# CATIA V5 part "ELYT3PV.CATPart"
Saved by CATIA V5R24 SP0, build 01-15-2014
Part number: ELYT3PV
Material "ZAMA": density 6700 kg/m3
Material "ZAMA": density 6700 kg/m3
Bounding box of the stored display mesh (mm): x -59 to 27.5, y 0 to 1560, z 0 to 1500
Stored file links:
  \\mnsrv021stg\Common\AREA TECNICA\Documenti\3D sito\BOX\ELYT\ZEPHYR3P\ELYT3PV.CATPart
  Z:\commesse\Novellini\Serie Zephiros\BH01S66\ID_18668_00.CATPart
  Z:\commesse\Novellini\Prove\Tabelladiprogetto1.txt
  Z:\commesse\Novellini\Prove\Tabelladiprogetto2.xls
  C:\Users\n.rebecchi\Desktop\Scambio\ID_35222_00.xls
  Z:\3D sito\BH02A.xlsx
  \\MNSRV021STG\Common\AREA TECNICA\Documenti\3D sito\BOX\ZEPHIROS\BH02A\BH02A.xls
  Z:\3D sito\ZEPHIROS\BH022P\BH022P.xls
  C:\Docisland\DocIsland\catia_workdir\diclient\N.REBECCHI\ID_21111_03.CATPart
  C:\Docisland\DocIsland\catia_workdir\diclient\N.REBECCHI\ID_29051_00.CATPart
  U:\AREA TECNICA\Documenti\3D sito\BOX\ZEPHYROS\ZEPHYR3P\BH013P.xls
  \\mnsrv021stg\Common\AREA TECNICA\Documenti\3D sito\BOX\ELYT\ZEPHYR3P\ELYT3PV.xls
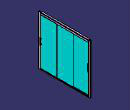
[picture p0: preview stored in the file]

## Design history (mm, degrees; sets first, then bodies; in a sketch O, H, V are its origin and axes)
Parameters
  `Larghezza anta` = 501 mm {design table}
  `MISURA NOMINALE` = 1560 mm {design table}
  PartNumber = "ELYT3PV156" {design table}
  `Lunghezza binario` = 1466 mm {design table}
Pad1: profile Sketch3.L13, length 1441, opposite side length -21
Solid1: solid without history
Solid2: solid without history
Pad2: profile Sketch3.L6, length 1441, opposite side length -21
Sketch1 on xy-plane, origin (0, 0, 0), H (1, 0, 0), V (0, 1, 0)
  axis line L1 (84.1025, 780) -> (-125.0839, 780)
  point P3 (-18.5, 0)
  point P4 (-18.5, 52.3)
  point P5 (0, 50.8)
  point P6 (-1.5, 52.3)
  point P8 (0, 1.5)
  point P9 (-1.5, 0)
  line L2 (0, 50.8) -> (0, 1.5)
  line L3 (-1.5, 0) -> (-32.75, 0)
  line L4 (-18.5, 1.5) -> (-18.5, 52.3)
  line L5 (-18.5, 52.3) -> (-1.5, 52.3)
  arc A1 centre (-1.5, 50.8) radius 1.5 from (0, 50.8) to (-1.5, 52.3) ccw
  arc A2 centre (-1.5, 1.5) radius 1.5 from (0, 1.5) to (-1.5, 0) cw
  line L6 (-18.5, 1.5) -> (-32.75, 1.5)
  point P11 (-32.75, 1.5)
  arc A3 centre (-32.75, 0.75) radius 0.75 from (-32.75, 1.5) to (-32.75, 0) ccw
  point P13 (-32.75, 0)
  point P14 (-18.5, 1.5)
  point P15 (-3, 1307.7)
  construction line L7 through (-1555.4, 0) direction (-1, 0)
  construction line L8 through (-1255.4, 0) direction (0, 1)
  point P16 (-18.5, 1560)
  point P17 (-18.5, 1507.7)
  point P18 (0, 1509.2)
  point P19 (-1.5, 1507.7)
  point P21 (0, 1558.5)
  point P22 (-1.5, 1560)
  point P24 (-32.75, 1558.5)
  point P26 (-32.75, 1560)
  point P27 (-18.5, 1558.5)
  line L9 (0, 1509.2) -> (0, 1558.5)
  line L10 (-1.5, 1560) -> (-32.75, 1560)
  line L11 (-18.5, 1558.5) -> (-18.5, 1509.1)
  line L12 (-52, 1507.7) -> (-1.5, 1507.7)
  arc A4 centre (-1.5, 1509.2) radius 1.5 from (0, 1509.2) to (-1.5, 1507.7) cw
  arc A5 centre (-1.5, 1558.5) radius 1.5 from (0, 1558.5) to (-1.5, 1560) ccw
  line L13 (-18.5, 1558.5) -> (-32.75, 1558.5)
  arc A6 centre (-32.75, 1559.25) radius 0.75 from (-32.75, 1558.5) to (-32.75, 1560) cw
  line L14 (-52, 1507.7) -> (-52, 1518.2)
  line L15 (-52, 1518.2) -> (-37, 1518.2)
  line L16 (-37, 1518.2) -> (-37, 1509.1)
  line L17 (-37, 1509.1) -> (-18.5, 1509.1)
  length L5 = 17
  radius A1 = 1.5
  distance L6 L3 = 1.5
  distance L4 A3 = 15
  distance L5 L3 = 52.3
  distance L2 L4 = 18.5
  radius A2 = 1.5
  distance L10 L3 = 1560 {= `MISURA NOMINALE`}
  distance L9 L14 = 52
  length L15 = 15
  distance L12 L17 = 1.4
  distance L15 L12 = 10.5
  tangency: A1 L2, A3 L3, A3 L6, L2 A2, A2 L3
  coincidence: P3 L3, P17 L11, P17 L12, L2 V, L3 L7, L3 H
  symmetry: P3 P16 L1, P4 P17 L1, P5 P18 L1, P6 P19 L1, P8 P21 L1, P9 P22 L1, P11 P24 L1, P13 P26 L1, P14 P27 L1, L2 L9 L1, L3 L10 L1, L4 L11 L1, L5 L12 L1, A1 A4 L1, A2 A5 L1, L6 L13 L1, A3 A6 L1
  vertical: L16 V
Pad3: profile Sketch1, direction (0, 0, 1), length 1500
Body1 "Telaio" (main body)
  Sketch2 on face of Pad3 from Sketch1.L5, origin (0, 52.3, 0), H (-1, 0, 0), V (0, 0, -1)
    point P1 (-1, -1500)
    line L1 (5.7859, -1500) -> (52.2221, -1500)
    line L2 (59, -1485.3692) -> (59, -1437.2118)
    construction line L3 (247.7599, -1440) -> (58, -1440)
    line L4 (-1, -1436.5) -> (-1, -1485.3692)
    point P2 (59, -1500)
    point P3 (59, -1440)
    construction line L5 (57.5, -1498) -> (57.5, -1486.5)
    construction line L6 (190.2599, -1498) -> (4.1139, -1498)
    point P5 (57.5, -1498)
    line L7 (57.7882, -1436) -> (-0.5, -1436)
    construction line L8 (8.597, -1485.5) -> (18.6226, -1485.5)
    construction line L9 (1.7786, -1486.5) -> (4.2562, -1486.5)
    construction line L10 (57.5, -1485.2) -> (57.5, -1440.5)
    construction line L11 (1, -1485) -> (1, -1464.277)
    point P6 (57.5, -1486.5)
    point P7 (1, -1485.5)
    construction line L12 (36.5779, -1495.9874) -> (36.5305, -1488.4874)
    construction line L13 (37.7781, -1496.0126) -> (37.7307, -1488.5126)
    construction line L14 (39.7307, -1486.5) -> (53.9552, -1486.5)
    construction line L15 (39.778, -1498) -> (50.7716, -1498)
    construction line L16 (18.9226, -1496) -> (18.9226, -1488.5)
    construction line L17 (20.1226, -1496) -> (20.1226, -1486.8)
    construction line L18 (20.4226, -1486.5) -> (34.5306, -1486.5)
    construction line L19 (22.1226, -1498) -> (34.5779, -1498)
    construction line L20 (18.9226, -1485.2) -> (18.9226, -1464.6071)
    construction line L21 (20.1226, -1485.2) -> (20.1226, -1466.4658)
    construction line L22 (36.5098, -1485.1981) -> (36.3815, -1464.8702)
    construction line L23 (37.7098, -1485.2019) -> (37.5963, -1467.2104)
    construction line L24 (20.4226, -1485.5) -> (222.4284, -1485.5)
    construction line L25 (38.0098, -1485.5) -> (57.2, -1485.5)
    construction line L26 (0.5, -1461.4168) -> (0.5, -1436.5)
    construction line L27 (46.4222, -1915.0185) -> (46.406, -1912.4534)
    construction line L28 (46.4222, -1915.0185) -> (47.9222, -1915.0091)
    construction arc A1 centre (8.7492, -1464.5115) radius 0.25 from (8.9992, -1464.5065) to (8.701, -1464.7568) cw
    construction arc A2 centre (5.7, -1465.25) radius 2.75 from (3.3803, -1463.773) to (8.3995, -1464.7254) cw
    point P12 (5.7, -1465.25)
    construction line L29 (1.4989, -1463.777) -> (3.3803, -1463.773)
    construction arc A3 centre (4.9238, -1464.5873) radius 4.0762 from (1.9856, -1461.762) to (9, -1464.5873) cw
    point P14 (8.9992, -1464.5065)
    construction arc A4 centre (8.7975, -1464.2662) radius 0.5 from (8.701, -1464.7568) to (8.321, -1464.4175) cw
    point P16 (8.321, -1464.4175)
    point P18 (23.1853, -1465.9683)
    point P19 (21.993, -1463.4903)
    point P20 (25.9312, -1465.8199)
    construction arc A5 centre (23.1853, -1465.9683) radius 2.75 from (21.993, -1463.4903) to (25.9123, -1465.6134) cw
    construction arc A6 centre (26.4305, -1465.7929) radius 0.5 from (25.9918, -1465.553) to (25.9312, -1465.8199) cw
    construction arc A7 centre (26.2112, -1465.6729) radius 0.25 from (26.45, -1465.7469) to (25.9918, -1465.553) cw
    construction arc A8 centre (23.4246, -1466.4658) radius 3.302 from (20.1226, -1466.4658) to (21.993, -1463.4903) cw
    point P24 (21.9929, -1463.4903)
    point P27 (40.6705, -1466.6867)
    construction arc A9 centre (43.6396, -1465.9948) radius 0.25 from (43.8765, -1466.0746) to (43.4818, -1466.1887) cw
    point P30 (43.3164, -1465.9372)
    construction arc A10 centre (43.7975, -1465.8009) radius 0.5 from (43.4818, -1466.1887) to (43.3164, -1465.9372) cw
    construction arc A11 centre (40.6705, -1466.6867) radius 2.75 from (39.5358, -1464.1817) to (43.3323, -1465.9959) cw
    construction arc A12 centre (40.8983, -1467.1895) radius 3.302 from (37.5963, -1467.2104) to (39.5358, -1464.1817) cw
    point P35 (211.7599, -1486.5)
    point P36 (12.6022, -1750.9456)
    point P37 (12.601, -1748.9456)
    point P38 (7.2208, -1496)
    point P39 (11.602, -1750.6462)
    point P40 (7.6073, -1494.5506)
    point P41 (7.6108, -1497.4484)
    point P42 (6.7699, -1497.6909)
    point P43 (5.9208, -1495.2516)
    point P44 (7.9723, -1497.2981)
    point P45 (5.9208, -1495.2516)
    point P46 (6.1845, -1494.2101)
    point P47 (7.9723, -1497.2981)
    point P48 (6.1845, -1494.2101)
    point P49 (6.7699, -1497.6909)
    point P50 (7.6073, -1494.5506)
    point P51 (7.6757, -1497.6898)
    point P52 (8.7353, -1495.1232)
    point P53 (5.9226, -1496.7516)
    point P54 (8.7353, -1495.1232)
    point P55 (5.9226, -1496.7516)
    point P56 (7.9692, -1494.7001)
    point P57 (7.9692, -1494.7001)
    point P58 (7.6108, -1497.4484)
    point P59 (7.6757, -1497.6898)
    construction arc A13 centre (7.2208, -1496) radius 1.5 from (7.6073, -1494.5506) to (7.6108, -1497.4484) ccw
    construction arc A14 centre (7.2208, -1496) radius 1.75 from (5.7042, -1495.1268) to (6.7699, -1497.6909) ccw
    construction line L30 (5.7042, -1495.1268) -> (5.9208, -1495.2516)
    construction arc A15 centre (7.2208, -1496) radius 1.5 from (7.9723, -1497.2981) to (5.9208, -1495.2516) ccw
    construction line L31 (6.1845, -1494.2101) -> (7.9723, -1497.2981)
    construction arc A16 centre (5.5354, -1494.5859) radius 0.75 from (6.1845, -1494.2101) to (5.5317, -1495.3359) ccw
    construction line L32 (6.7699, -1497.6909) -> (7.6073, -1494.5506)
    construction arc A17 centre (7.2208, -1496) radius 1.75 from (7.6757, -1497.6898) to (8.7353, -1495.1232) ccw
    construction line L33 (5.9226, -1496.7516) -> (8.7353, -1495.1232)
    construction arc A18 centre (7.2208, -1496) radius 1.5 from (5.9226, -1496.7516) to (7.9692, -1494.7001) ccw
    construction line L34 (7.9692, -1494.7001) -> (8.2527, -1494.2076)
    construction arc A19 centre (8.9027, -1494.5818) radius 0.75 from (9.4761, -1494.0984) to (8.2527, -1494.2076) ccw
    construction arc A20 centre (7.2208, -1496) radius 2.95 from (4.9609, -1494.1038) to (5.5608, -1493.5613) ccw
    construction line L35 (7.6108, -1497.4484) -> (7.6757, -1497.6898)
    point P60 (196.5645, -1917.6542)
    point P61 (11.6031, -1752.3962)
    point P62 (167.077, -1877.6984)
    construction line L36 (7.2208, -1496) -> (7.769, -1950.7895)
    point P63 (7.769, -1950.7895)
    construction line L37 (7.2208, -1496) -> (-0.9278, -1496)
    point P65 (4.9609, -1494.1038)
    point P67 (7.2232, -1498)
    construction line L38 (10.3276, -1498) -> (16.9226, -1498)
    construction arc A21 centre (4.1139, -1497.5) radius 0.5 from (4.5642, -1497.2826) to (4.1139, -1498) cw
    point P68 (4.5642, -1497.2826)
    construction arc A22 centre (7.2208, -1496) radius 2.95 from (9.4761, -1494.0984) to (9.8774, -1497.2826) cw
    construction arc A23 centre (10.3276, -1497.5) radius 0.5 from (9.8774, -1497.2826) to (10.3276, -1498) ccw
    point P74 (195.3181, -1910.0413)
    point P75 (197.3181, -1910.0413)
    point P77 (195.6181, -1911.0413)
    point P78 (193.8681, -1911.0413)
    point P79 (194.0428, -1910.0413)
    construction line L39 (198.7599, -1909.6171) -> (198.7599, -1904.8275)
    point P81 (196.7599, -1907.6171)
    construction line L40 (7.5212, -1762.7716) -> (7.5105, -1745.0224)
    point P85 (2.4259, -1750.9517)
    point P86 (2.4247, -1748.9517)
    point P88 (3.4257, -1750.6511)
    point P89 (3.4268, -1752.4011)
    point P90 (-151.896, -1877.8906)
    point P91 (7.5, -1950.7897)
    construction line L41 (7.5, -1935.9877) -> (7.5, -1950.7897)
    point P92 (7.5, -1497.9998)
    point P93 (2.4259, -1750.9517)
    point P94 (2.4247, -1748.9517)
    point P95 (7.5, -1487)
    point P96 (3.4257, -1750.6511)
    point P97 (7.8882, -1488.4489)
    point P98 (7.1118, -1488.4489)
    point P99 (7.9529, -1488.6904)
    point P100 (8.799, -1486.25)
    point P101 (8.25, -1485.701)
    point P102 (8.799, -1486.25)
    point P103 (8.5378, -1485.2025)
    point P104 (8.25, -1485.701)
    point P105 (8.5378, -1485.2025)
    point P106 (7.9529, -1488.6904)
    point P107 (7.8882, -1488.4489)
    point P108 (7.0471, -1488.6904)
    point P109 (5.9845, -1486.125)
    point P110 (6.201, -1486.25)
    point P111 (5.9845, -1486.125)
    point P112 (6.201, -1486.25)
    point P113 (6.75, -1485.701)
    point P114 (6.75, -1485.701)
    point P115 (7.1118, -1488.4489)
    point P116 (7.0471, -1488.6904)
    point P117 (3.4268, -1752.4011)
    point P118 (-151.896, -1877.8906)
    point P119 (7.5, -1950.7897)
    construction line L42 (7.5, -1487) -> (7.5, -1950.7897)
    point P120 (6.4659, -1485.2089)
    point P121 (7.5, -1497.9998)
    construction arc A24 centre (7.5, -1487) radius 1.5 from (7.8882, -1488.4489) to (7.1118, -1488.4489) cw
    construction arc A25 centre (7.5, -1487) radius 1.75 from (9.0155, -1486.125) to (7.9529, -1488.6904) cw
    construction line L43 (9.0155, -1486.125) -> (8.799, -1486.25)
    construction arc A26 centre (7.5, -1487) radius 1.5 from (8.25, -1485.701) to (8.799, -1486.25) cw
    construction line L44 (8.2506, -1485.7) -> (8.25, -1485.701)
    construction arc A27 centre (9.1873, -1485.5775) radius 0.75 from (8.5378, -1485.2025) to (9.6782, -1485.0105) cw
    construction line L45 (7.9529, -1488.6904) -> (7.8882, -1488.4489)
    construction arc A28 centre (7.5, -1487) radius 1.75 from (7.0471, -1488.6904) to (5.9845, -1486.125) cw
    construction line L46 (6.201, -1486.25) -> (5.9845, -1486.125)
    construction arc A29 centre (7.5, -1487) radius 1.5 from (6.201, -1486.25) to (6.75, -1485.701) cw
    construction line L47 (6.75, -1485.701) -> (6.7494, -1485.7)
    construction arc A30 centre (5.8164, -1485.5839) radius 0.75 from (5.2424, -1485.1011) to (6.4659, -1485.2089) cw
    construction arc A31 centre (7.5, -1487) radius 2.95 from (5.0963, -1485.2898) to (5.2424, -1485.1011) cw
    construction line L48 (7.1118, -1488.4489) -> (7.0471, -1488.6904)
    construction arc A32 centre (7.5, -1487) radius 2.95 from (4.5556, -1486.8185) to (10.45, -1487) ccw
    construction arc A33 centre (4.2562, -1486.8) radius 0.3 from (4.5556, -1486.8185) to (4.2562, -1486.5) ccw
    construction line L49 (16.9226, -1486.5) -> (10.95, -1486.5)
    construction arc A34 centre (10.95, -1487) radius 0.5 from (10.45, -1487) to (10.95, -1486.5) cw
    construction arc A35 centre (10.7882, -1483.9966) radius 1.5034 from (9.6782, -1485.0105) to (10.7882, -1485.5) ccw
    point P129 (9.6782, -1485.0105)
    point P130 (10.7882, -1485.5)
    construction line L50 (1.5, -1485.5) -> (6.403, -1485.5)
    construction arc A36 centre (4.6889, -1485) radius 0.5 from (5.0963, -1485.2898) to (4.6889, -1485.5) cw
    point P134 (4.6889, -1485.5)
    point P136 (9.6782, -1485.0105)
    construction arc A37 centre (6.403, -1485.9) radius 0.4 from (6.403, -1485.5) to (6.7494, -1485.7) cw
    construction arc A38 centre (8.597, -1485.9) radius 0.4 from (8.597, -1485.5) to (8.2506, -1485.7) ccw
    construction line L51 (191.961, -1463.0884) -> (240.5943, -1463.7586)
    construction line L52 (194.4697, -1470.2529) -> (261.0074, -1472.9865)
    construction circle A39 centre (7.2208, -1496) radius 1.75
    construction arc A40 centre (-0.5, -1499.5) radius 0.5 from (-1, -1499.5) to (-0.5, -1500) ccw
    point P147 (-1, -1499.5)
    point P148 (-0.5, -1500)
    construction arc A41 centre (58.5, -1499.5) radius 0.5 from (58.5, -1500) to (59, -1499.5) ccw
    point P150 (58.5, -1500)
    point P151 (59, -1499.5)
    arc A42 centre (-0.5, -1436.5) radius 0.5 from (-1, -1436.5) to (-0.5, -1436) cw
    construction arc A43 centre (0, -1436.5) radius 0.5 from (0, -1436) to (0.5, -1436.5) cw
    point P156 (0, -1436)
    construction arc A44 centre (58, -1440.5) radius 0.5 from (57.5, -1440.5) to (58, -1440) cw
    line L53 (-0.9205, -1485.76) -> (4.8654, -1499.3908)
    point P163 (-1, -1485.5727)
    arc A45 centre (5.7859, -1499) radius 1 from (4.8654, -1499.3908) to (5.7859, -1500) ccw
    point P164 (4.8654, -1499.3908)
    point P165 (5.7859, -1500)
    construction arc A46 centre (5.5292, -1495.8359) radius 0.5 from (5.5317, -1495.3359) to (5.0689, -1496.0313) cw
    construction arc A47 centre (1.7786, -1487) radius 0.5 from (1.3183, -1487.1954) to (1.7786, -1486.5) cw
    construction arc A48 centre (1.5, -1485) radius 0.5 from (1, -1485) to (1.5, -1485.5) ccw
    construction arc A49 centre (18.6226, -1485.2) radius 0.3 from (18.9226, -1485.2) to (18.6226, -1485.5) cw
    construction arc A50 centre (20.4226, -1485.2) radius 0.3 from (20.1226, -1485.2) to (20.4226, -1485.5) ccw
    construction arc A51 centre (16.9226, -1488.5) radius 2 from (16.9226, -1486.5) to (18.9226, -1488.5) cw
    construction line L54 (29, -1900.3555) -> (29, -1979.6079)
    point P187 (53.1346, -1499.3908)
    line L55 (58.9205, -1485.76) -> (53.1346, -1499.3908)
    arc A52 centre (52.2141, -1499) radius 1 from (53.1345, -1499.3908) to (52.2221, -1500) cw
    point P190 (59, -1485.5727)
    construction line L56 (55.7962, -1489.2815) -> (52.6126, -1496.7815)
    point P191 (-104.6902, -1867.3637)
    point P192 (-110.5556, -1881.1818)
    construction line L57 (59, -1485.5727) -> (-104.6902, -1867.3637)
    construction line L58 (53.1346, -1499.3908) -> (-110.5556, -1881.1818)
    construction line L59 (1.0011, -1461.9168) -> (1.6263, -1461.9155)
    construction arc A53 centre (1, -1461.4168) radius 0.5 from (0.5, -1461.4168) to (1.0011, -1461.9168) ccw
    construction arc A54 centre (1.6252, -1461.4155) radius 0.5 from (1.9856, -1461.762) to (1.6263, -1461.9155) cw
    construction arc A55 centre (22.7726, -1464.6071) radius 3.85 from (18.9226, -1464.6071) to (26.6226, -1464.6074) cw
    construction arc A56 centre (40.2297, -1464.8459) radius 3.8483 from (36.3815, -1464.8702) to (44.0779, -1464.8216) cw
    point P202 (40.2827, -1460.998)
    point P204 (43.8765, -1466.0746)
    point P205 (26.45, -1465.7469)
    arc A57 centre (0, -1485.3692) radius 1 from (-1, -1485.3692) to (-0.9205, -1485.76) ccw
    arc A58 centre (58, -1485.3692) radius 1 from (59, -1485.3692) to (58.9205, -1485.76) cw
    construction arc A59 centre (36.2098, -1485.2) radius 0.3 from (36.5098, -1485.1981) to (36.2098, -1485.5) cw
    construction arc A60 centre (38.0098, -1485.2) radius 0.3 from (37.7098, -1485.2019) to (38.0098, -1485.5) ccw
    construction arc A61 centre (39.7307, -1488.5) radius 2 from (37.7307, -1488.5126) to (39.7307, -1486.5) cw
    construction arc A62 centre (34.5306, -1488.5) radius 2 from (34.5306, -1486.5) to (36.5305, -1488.4874) cw
    construction arc A63 centre (34.5779, -1496) radius 2 from (36.5779, -1495.9874) to (34.5779, -1498) cw
    construction arc A64 centre (39.778, -1496) radius 2 from (37.7781, -1496.0126) to (39.778, -1498) ccw
    construction arc A65 centre (22.1226, -1496) radius 2 from (20.1226, -1496) to (22.1226, -1498) ccw
    construction arc A66 centre (16.9226, -1496) radius 2 from (18.9226, -1496) to (16.9226, -1498) cw
    construction arc A67 centre (50.7716, -1496) radius 2 from (52.6126, -1496.7815) to (50.7716, -1498) cw
    construction arc A68 centre (57.2, -1485.2) radius 0.3 from (57.5, -1485.2) to (57.2, -1485.5) cw
    construction arc A69 centre (1.5, -1464.277) radius 0.5 from (1, -1464.277) to (1.4989, -1463.777) cw
    construction arc A70 centre (53.9552, -1488.5) radius 2 from (53.9552, -1486.5) to (55.7962, -1489.2815) cw
    construction line L60 (1.3183, -1487.1954) -> (5.0689, -1496.0313)
    point P247 (162.3117, -1866.472)
    point P248 (168.0976, -1880.1028)
    construction line L61 (-0.9205, -1485.76) -> (162.3117, -1866.472)
    construction line L62 (4.8654, -1499.3908) -> (168.0976, -1880.1028)
    construction line L63 (57.3536, -1460.1464) -> (55.6464, -1461.8536)
    point P251 (57.5, -1460)
    construction line L64 (55.5, -1462.2071) -> (55.5, -1485)
    point P252 (55.5, -1485.5)
    construction arc A71 centre (55, -1485) radius 0.5 from (55.5, -1485) to (55, -1485.5) cw
    point P254 (55, -1485.5)
    construction arc A72 centre (56, -1462.2071) radius 0.5 from (55.5, -1462.2071) to (55.6464, -1461.8536) cw
    construction arc A73 centre (57, -1459.7929) radius 0.5 from (57.5, -1459.7929) to (57.3536, -1460.1464) cw
    point P259 (57.5, -1459.7929)
    construction line L65 (9, -1464.5873) -> (9, -1465.2632)
    construction arc A74 centre (8.7, -1465.2632) radius 0.3 from (9, -1465.2632) to (8.4, -1465.2632) cw
    construction line L66 (8.3995, -1464.7254) -> (8.4, -1465.2632)
    axis line L67 (204.6582, -1469.5884) -> (238.7986, -1470.2896)
    construction line L68 (26.6226, -1464.6074) -> (26.6225, -1465.5674)
    construction arc A75 centre (26.2659, -1465.5674) radius 0.3566 from (25.9123, -1465.6134) to (26.6225, -1465.5674) ccw
    construction line L69 (44.0779, -1464.8216) -> (44.0847, -1465.8974)
    construction arc A76 centre (43.7024, -1465.8999) radius 0.3823 from (43.3323, -1465.9959) to (44.0847, -1465.8974) ccw
    point P279 (213.6284, -1912.5175)
    point P280 (222.8519, -1905.6947)
    point P281 (220.8519, -1903.6947)
    point P282 (222.4284, -1485.5)
    point P283 (222.4284, -1485.5)
    construction line L70 (222.4284, -1485.5) -> (36.2098, -1485.5)
    construction arc A77 centre (20.4226, -1486.8) radius 0.3 from (20.1226, -1486.8) to (20.4226, -1486.5) cw
    arc A78 centre (57.7882, -1437.2118) radius 1.2118 from (57.7882, -1436) to (59, -1437.2118) cw
    point P290 (0, 0)
    point P291 (0, 0)
    point P304 (0.6, -33)
    line L71 (0.5, 0) -> (48.5, 0)
    line L72 (50, -1.5) -> (50, -11.2929)
    line L73 (0, -17.5) -> (48.1743, -13.2853)
    line L74 (-0.5, -35) -> (0.0954, -35)
    line L75 (-1, -34.5) -> (-1, -1.5)
    arc A79 centre (0.5, -1.5) radius 1.5 from (-1, -1.5) to (0.5, 0) cw
    line L76 (0, -32.0835) -> (0, -17.5)
    arc A80 centre (-0.5, -34.5) radius 0.5 from (-1, -34.5) to (-0.5, -35) ccw
    arc A81 centre (48, -11.2929) radius 2 from (48.1743, -13.2853) to (50, -11.2929) ccw
    line L77 (0.6, -34.4954) -> (0.6, -33)
    arc A82 centre (0.0954, -34.4954) radius 0.5046 from (0.0954, -35) to (0.6, -34.4954) ccw
    arc A83 centre (0.1, -33) radius 0.5 from (0.3, -32.5417) to (0.6, -33) cw
    arc A84 centre (0.5, -32.0835) radius 0.5 from (0.3, -32.5417) to (0, -32.0835) cw
    arc A85 centre (48.5, -1.5) radius 1.5 from (50, -1.5) to (48.5, 0) ccw
    reference intersected line E1 through (0, 0) direction (0, -1) from face of Pad3 from Sketch1.L2
    reference intersected line E2 (18.5, -1500) -> (1.5, -1500) from end face of Pad3
    point P312 (0, -17.5)
    distance L2 L5 = 1.5
    distance L1 L6 = 2
    distance L8 L9 = 1
    distance L20 L21 = 1.2
    distance L22 L23 = 1.2
    distance L11 L20 = 17.9226 (reference)
    distance L23 L27 = 6
    radius A1 = 0.25
    radius A2 = 2.75
    distance L11 P12 = 4.7 (reference)
    radius A4 = 0.5
    radius A7 = 0.25
    radius A6 = 0.5
    radius A5 = 2.75
    radius A11 = 2.75
    radius A9 = 0.25
    radius A10 = 0.5
    radius A14 = 1.75
    distance A14 A15 = 0.25
    radius A13 = 1.5
    radius A20 = 2.95
    angle L31 L36 = 330
    angle L34 L31 = 60
    angle L30 L31 = 30
    angle L32 L35 = 30
    angle L35 L33 = 105
    radius A19 = 0.75
    radius A16 = 0.75
    angle L34 L33 = 30
    angle L31 L30 = 30 (reference)
    radius A21 = 0.5
    radius A23 = 0.5
    distance P38 P95 = 9
    radius A33 = 0.3
    radius A34 = 0.5
    radius A35 = 1.5034
    radius A28 = 1.75
    radius A32 = 2.95
    radius A29 = 1.5
    radius A36 = 0.5
    angle L47 L44 = 60
    radius A30 = 0.75
    angle L44 L43 = 30
    radius A27 = 0.75
    angle L42 L48 = 15
    radius A37 = 0.4
    radius A38 = 0.4
    distance P12 L50 = 20.25
    distance L29 P12 = 1.482
    distance A3 L29 = 3.2585
    distance L29 A1 = 1
    distance P18 P27 = 17.5
    radius A12 = 3.302
    radius A8 = 3.302
    radius A3 = 4.0762
    distance A3 P12 V = 3.4134 (reference)
    distance P18 P12 = 17.5
    distance L1 P38 = 4
    radius A40 = 0.5
    distance P2 P3 = 60
    radius A41 = 0.5
    radius A42 = 0.5
    radius A43 = 0.5
    radius A44 = 0.5
    distance L4 P95 = 8.5
    radius A45 = 1
    angle L53 L4 = 157
    distance L4 P165 = 6.7859
    distance P163 L1 = 14.4273 (reference)
    radius A46 = 0.5
    radius A47 = 0.5
    radius A48 = 0.5
    distance L22 P27 = 4.2774
    radius A49 = 0.3
    radius A50 = 0.3
    radius A51 = 2
    distance L4 L26 = 1.5
    length L4 = 48.8692 (reference)
    distance L55 L56 = 1.5
    radius A53 = 0.5
    radius A54 = 0.5
    distance L29 L59 = 1.8612
    distance L11 L4 = 2
    distance L20 A55 = 7.7
    radius A9 = 0.25 (reference)
    distance L22 L69 = 7.6965
    radius A57 = 1
    radius A58 = 1
    radius A59 = 0.3
    radius A60 = 0.3
    radius A61 = 2
    radius A62 = 2
    radius A63 = 2
    radius A64 = 2
    radius A65 = 2
    radius A66 = 2
    radius A67 = 2
    radius A68 = 0.3
    radius A69 = 0.5
    radius A70 = 2
    distance L53 L60 = 1.5
    distance L16 L17 = 1.2 (reference)
    distance L20 L16 = 0
    distance L21 L17 = 0
    distance L22 L12 = 0
    distance L13 L23 = 0
    distance L12 L13 = 1.2 (reference)
    distance L1 L25 = 14.5
    distance P251 L3 = 20
    distance L2 L64 = 3.5
    angle L63 L10 = 135
    radius A71 = 0.5
    radius A72 = 0.5
    radius A73 = 0.5
    radius A74 = 0.3
    distance A74 L51 = 5
    distance L11 L65 = 8 (reference)
    radius A75 = 0.3566 (reference)
    radius A76 = 0.3823 (reference)
    distance L20 L65 = 9.9226
    distance L65 P12 = 3.3
    distance L4 P12 = 6.7
    distance L1 L7 = 64
    radius A77 = 0.3
    radius A78 = 1.2118
    distance L1 H = 1500 (reference)
    distance L71 L74 = 35
    distance L75 E1 = 1
    distance L75 L72 = 51
    distance L75 L76 = 1
    radius A85 = 1.5
    radius A81 = 2
    radius A80 = 0.5
    radius A82 = 0.5046
    distance L75 L77 = 1.6
    radius A83 = 0.5
    radius A84 = 0.5
    radius A79 = 1.5
    distance L2 L4 = 60
    angle L71 L73 = 5
    distance L71 P312 = 17.5
    distance L74 P304 = 2
    coincidence: L5 L10, L9 L14, L6 L15, L9 L18, L6 L19, L8 L24, L24 L25, A8 P24, P24 A5, A8 P19, P19 A5, A14 A17, A13 A15, A18 A13, L34 P38, L31 P38, P47 P44, P43 P45, P59 P51, P49 P42, L32 P38, L35 P38, L33 P38, P53 P55, P54 P52, P57 P56, P48 P46, L30 P38, P41 P58, P40 L32, L6 L38, L36 P67, L6 P67, L38 P67, P102 P100, P104 P101, P105 P103, P106 P99, P107 P97, P111 P109, P112 P110, P114 P113, P115 P98, P116 P108, L9 P35, L8 P7, A28 A25, A26 A24, A29 A26, P129 A31, P136 P129, A31 A32, L44 P95, L43 P95, L48 P95, L50 P134, L47 P120, L8 P130, L44 P103, L8 L50, L4 P1, L1 P1, L1 P2, L2 P2, L3 P3, L2 P3, P147 L4, P148 L1, A20 P68, A16 P65, L11 P7, L50 P7, L49 P35, P150 L1, P151 L2, P192 L56, P5 L15, P191 L56, P6 L14, A56 P202, P202 L51, L4 P163, L53 P163, L2 P190, L55 P190, L60 P62, P247 L60, P248 L60, P251 L10, P252 L25, P251 L63, L64 P252, P14 A3, P16 A2, A5 P20, P205 A55, A11 P30, P204 A56, P259 L10, P254 L25, L24 P282, L24 L70, P283 P282, L7 P156, P50 P40, L71 H, L4 L75, L1 E2
    tangency: A3 A1, A4 A1, A2 A4, A5 A6, A6 A7, A11 A10, A10 A9, A19 L34, A16 L31, A19 A20, A16 A20, A21 L6, A21 A20, A22 A16, A23 A22, A23 L38, A33 A32, A33 L9, L49 A33, A34 A32, A34 L49, A35 A31, A35 L8, L50 A24, A36 A31, A36 L50, L44 A27, L47 A30, A31 A30, A37 L50, A37 L47, A38 L8, A38 L44, L51 A3, L52 A2, L52 A5, A11 L52, A8 A5, A11 A12, A8 L21, A12 L23, A40 L4, A40 L1, A41 L1, A41 L2, A42 L4, A42 L7, A43 L7, A43 L26, A44 L10, A44 L3, A45 L53, A45 L1, A46 A16, A47 L9, A48 L11, A48 L50, A49 L20, A49 L8, A50 L21, A50 L24, A51 L49, A51 L16, A53 L26, A53 L59, A54 L59, A54 A3, A55 L51, L20 A55, A55 A7, A56 L22, A56 L51, A9 A56, A57 L4, A57 L53, A58 L2, A58 L55, A59 L22, A59 L24, A60 L23, A60 L25, A61 L13, A61 L14, A62 L18, A62 L12, A63 L12, A63 L19, A64 L13, A64 L15, A65 L17, A65 L19, A66 L16, A66 L38, A67 L56, A67 L15, A68 L10, A68 L25, A69 L11, A69 L29, A70 L14, A70 L56, A47 L60, A46 L60, A71 L64, A71 L25, A72 L64, A72 L63, A73 L10, A73 L63, L65 A3, L66 A74, L65 A74, L67 A74, A7 L67, L68 A55, A75 L68, A75 A5, A75 L67, L69 A56, A76 L69, A76 A11, L67 A76, A77 L17, A77 L18, A78 L7, A78 L2, L71 A85, L72 A85, L72 A81, A81 L73, A84 L76, L77 A83, L71 A79, L75 A79, A83 A84
    concentricity: A17 A14, A14 P38, P38 A39, A20 A14, A32 A28, A28 P95, A26 A24, A29 A28
    symmetry: P36 P85 L40, P37 P86 L40, P39 P88 L40, P61 P89 L40, P62 P90 L40, P63 P91 L40, L36 L41 L40, P67 P92 L40, P36 P93 L40, P37 P94 L40, P39 P96 L40, P61 P117 L40, P62 P118 L40, P63 P119 L40, L36 L42 L40, P67 P121 L40, L47 L44 L42, L46 L43 L42, L48 L45 L42, L4 L2 L54, P164 P187 L54, L53 L55 L54, A45 A52 L54
  Pad4: profile Sketch2, direction (0, 1, 0), up to face of Pad3 from Sketch1.L12
Body2 "Maniglia sx"
Body3 "Vetro sx"
Body4 "maniglia dx"
Body5 "Vetro centrale"
  Pad5: profile Sketch3.L2, length 1441, opposite side length -21
  Sketch3 on xy-plane, origin (0, 0, 0), H (1, 0, 0), V (0, 1, 0)
    point P1 (-22, 627.7)
    line L1 (-19, 528.9303) -> (-24.9999, 528.9592)
    line L2 (-25, 528.9592) -> (-25, 1029.9592)
    line L3 (-25, 1029.9592) -> (-19, 1029.9379)
    line L4 (-19, 1029.9379) -> (-19, 528.9303)
    point P6 (-39.5, 1257.2061)
    line L5 (-36.5, 1006.7) -> (-42.5, 1006.7213)
    line L6 (-42.5, 1006.7213) -> (-42.5, 1507.7)
    line L7 (-42.5, 1507.7) -> (-36.5, 1507.7)
    line L8 (-36.5, 1507.7) -> (-36.5, 1006.7)
    construction line L9 (-39.5, 1257.2061) -> (-39.5, -213.0288)
    point P12 (-4.5, 301.6521)
    line L10 (-1.5, 51.1464) -> (-7.5, 51.1464)
    line L11 (-7.5, 51.1464) -> (-7.5, 552.1752)
    line L12 (-7.5, 552.1752) -> (-1.5, 552.1464)
    line L13 (-1.5, 552.1464) -> (-1.5, 51.1464)
    construction line L14 (-4.5, 301.6521) -> (-122.8046, 301.6521)
    point P18 (4, -1)
    point P19 (4, 1038.4)
    axis line L15 (-22, 627.7) -> (-154.4866, 627.7)
    reference projected line E1 (-1.5, 1507.7) -> (-48.1743, 1507.7) from edge [face of Pad3 from Sketch1.L12 | face of Pad4 from Sketch2.L73]
    length L2 = 501 {= `Larghezza anta`}
    length L8 = 501 {= `Larghezza anta`}
    length L1 = 6
    length L5 = 6
    length L10 = 6
    length L13 = 501 {= `Larghezza anta`}
    distance L13 L4 = 17.5
    distance L8 L4 = 17.5
    distance L3 L5 = 23.3
    distance L12 L1 = 23.3
    distance L13 V = 1.5
    distance L11 L13 = 6
    distance L4 L2 = 6
    distance L6 L8 = 6
    distance L7 E1 = 0
    equidistance: L2 L4 P1, L5 L7 P6, L6 L8 P6, L10 L12 P12, L11 L13 P12
    vertical: L9 V
Body6 "Vetro dx"
Relations
  design table, configuration 1, drives `Larghezza anta`, `MISURA NOMINALE`, PartNumber, `Lunghezza binario`
  Value = `Larghezza anta`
